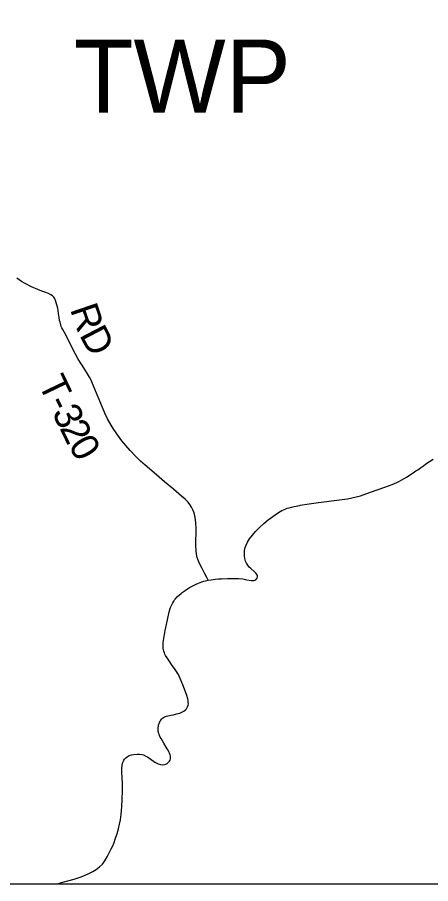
# Model space of a CAD drawing. Extents: x -10.5 to 40.6, y -3.2 to 22.
# Drawn here: x -6.111 to -5.263, y 14.1 to 15.878 of the extents above; entities that cross this region are included whole.
import ezdxf

# ---------------------------------------------------------------- set-up
doc = ezdxf.new("R2010")
doc.units = 0
for name, color, linetype in [('GM_X_County_Road', 7, 'Continuous'), ('GM_X_Township_Road', 7, 'Continuous'), ('GM_X_Township_Road_Text', 7, 'Continuous'), ('GM_X_Township_Text', 7, 'Continuous')]:
    doc.layers.add(name, color=color, linetype=linetype)

msp = doc.modelspace()

# ---------------------------------------------------------------- linework, layer by layer
at = {"layer": 'GM_X_County_Road'}
for points in [[(-5.7194, 14.7225), (-5.7136, 14.7237), (-5.7049, 14.7248), (-5.6982, 14.7254), (-5.6924, 14.7254), (-5.68, 14.7259), (-5.6651, 14.7263), (-5.6571, 14.7261), (-5.6484, 14.7252), (-5.6398, 14.7237), (-5.6313, 14.7221), (-5.6289, 14.7219), (-5.627, 14.7219), (-5.6254, 14.7222), (-5.6234, 14.7227), (-5.6216, 14.7237), (-5.6193, 14.7261), (-5.6189, 14.727), (-5.6181, 14.7296), (-5.6185, 14.7323), (-5.6193, 14.7343), (-5.6209, 14.7366), (-5.6253, 14.7408), (-5.6319, 14.7466), (-5.6351, 14.7497), (-5.6382, 14.7537), (-5.6406, 14.7574), (-5.6428, 14.762), (-5.6443, 14.7675), (-5.645, 14.7726), (-5.6452, 14.7783), (-5.6446, 14.7839), (-5.6433, 14.7895), (-5.6417, 14.7943), (-5.6387, 14.8006), (-5.6344, 14.8075), (-5.6287, 14.815), (-5.6223, 14.8226), (-5.6144, 14.8306), (-5.6052, 14.839), (-5.596, 14.8465), (-5.5816, 14.8571), (-5.5754, 14.8613), (-5.5684, 14.8655), (-5.5615, 14.8686), (-5.5575, 14.8702), (-5.5529, 14.8715), (-5.5481, 14.8728), (-5.5429, 14.874), (-5.5315, 14.8763), (-5.5307, 14.8764), (-5.5123, 14.8796), (-5.4932, 14.8823), (-5.4556, 14.8871), (-5.4335, 14.8898), (-5.4243, 14.8915), (-5.4153, 14.8936), (-5.4064, 14.8961), (-5.3859, 14.9031), (-5.3565, 14.9134), (-5.342, 14.9189), (-5.3324, 14.9231), (-5.3268, 14.9256), (-5.322, 14.9284), (-5.3124, 14.9341), (-5.2984, 14.9432), (-5.2933, 14.9468), (-5.2892, 14.9495), (-5.2834, 14.9535), (-5.2775, 14.9577), (-5.2723, 14.9612), (-5.2652, 14.966), (-5.2574, 14.9712)], [(-5.8117, 14.5951), (-5.8107, 14.6032), (-5.8078, 14.6192), (-5.8032, 14.6411), (-5.7992, 14.6581), (-5.7966, 14.6664), (-5.7936, 14.6734), (-5.7921, 14.6765), (-5.7902, 14.6794), (-5.7883, 14.6823), (-5.787, 14.6841), (-5.7824, 14.6893), (-5.7785, 14.693), (-5.7752, 14.6956), (-5.7727, 14.6973), (-5.7667, 14.7017), (-5.762, 14.7048), (-5.7578, 14.7074), (-5.7479, 14.7127), (-5.7439, 14.7147), (-5.7395, 14.7166), (-5.7357, 14.7181), (-5.7323, 14.7193), (-5.7286, 14.7204), (-5.7249, 14.7216), (-5.7194, 14.7225)], [(-6.0287, 14.1), (-6.0205, 14.1022), (-5.9942, 14.1094), (-5.9824, 14.1131), (-5.9732, 14.1168), (-5.9631, 14.1216), (-5.956, 14.1252), (-5.9492, 14.1294), (-5.9424, 14.1346), (-5.9367, 14.1403), (-5.9319, 14.1466), (-5.9268, 14.155), (-5.9225, 14.1631), (-5.9184, 14.1712), (-5.916, 14.1764), (-5.9127, 14.1842), (-5.9103, 14.191), (-5.9063, 14.2027), (-5.9035, 14.2122), (-5.9012, 14.2218), (-5.8996, 14.2309), (-5.8982, 14.242), (-5.897, 14.2574), (-5.8961, 14.2735), (-5.8955, 14.2896), (-5.8955, 14.3057), (-5.896, 14.3175), (-5.8966, 14.3287), (-5.8967, 14.3363), (-5.8961, 14.3426), (-5.8951, 14.347), (-5.8936, 14.3511), (-5.8923, 14.3533), (-5.891, 14.3555), (-5.8883, 14.3583), (-5.8858, 14.3604), (-5.8813, 14.3628), (-5.877, 14.3641), (-5.872, 14.3651), (-5.865, 14.3656), (-5.8602, 14.3657), (-5.8558, 14.365), (-5.8525, 14.3641), (-5.8472, 14.3619), (-5.8439, 14.3601), (-5.8413, 14.3582), (-5.8362, 14.3546), (-5.8316, 14.3513), (-5.8292, 14.3495), (-5.8259, 14.3478), (-5.8221, 14.346), (-5.8175, 14.3446), (-5.8127, 14.344), (-5.8091, 14.3445), (-5.8063, 14.3452), (-5.8037, 14.3464), (-5.8014, 14.3483), (-5.7987, 14.3513), (-5.7978, 14.3535), (-5.7969, 14.356), (-5.7966, 14.3581), (-5.7971, 14.3617), (-5.7978, 14.3642), (-5.7991, 14.3676), (-5.8004, 14.3708), (-5.8019, 14.3737), (-5.8035, 14.377), (-5.8054, 14.3802), (-5.8107, 14.3886), (-5.8162, 14.3976), (-5.8179, 14.4009), (-5.8192, 14.4038), (-5.8203, 14.4069), (-5.8212, 14.4098), (-5.8218, 14.4142), (-5.822, 14.4164), (-5.822, 14.4193), (-5.8215, 14.4237), (-5.8211, 14.4262), (-5.8203, 14.4287), (-5.8189, 14.4322), (-5.8178, 14.4342), (-5.8168, 14.4357), (-5.8154, 14.4376), (-5.8135, 14.4394), (-5.8113, 14.4411), (-5.8091, 14.4423), (-5.8073, 14.443), (-5.8052, 14.4437), (-5.7959, 14.4459), (-5.7907, 14.4467), (-5.7843, 14.4482), (-5.7779, 14.45), (-5.7734, 14.4519), (-5.7692, 14.4543), (-5.766, 14.457), (-5.764, 14.4591), (-5.7627, 14.4612), (-5.7616, 14.4632), (-5.7606, 14.4665), (-5.7601, 14.4693), (-5.7602, 14.4727), (-5.7605, 14.4764), (-5.7611, 14.4794), (-5.7631, 14.4859), (-5.7702, 14.5044), (-5.7746, 14.516), (-5.7768, 14.5208), (-5.7789, 14.5256), (-5.7806, 14.5289), (-5.7825, 14.5321), (-5.7845, 14.5356), (-5.7871, 14.5394), (-5.7946, 14.55), (-5.7997, 14.557), (-5.8039, 14.5633), (-5.8067, 14.5682), (-5.8081, 14.571), (-5.8092, 14.5739), (-5.8102, 14.5769), (-5.811, 14.5801), (-5.8115, 14.5835), (-5.8119, 14.5876), (-5.812, 14.5917), (-5.8117, 14.5951)]]:
    msp.add_lwpolyline(points, dxfattribs=at)
at = {"layer": 'GM_X_Township_Road'}
msp.add_lwpolyline([(-5.7194, 14.7225), (-5.7222, 14.7282), (-5.726, 14.736), (-5.7327, 14.7479), (-5.7374, 14.7573), (-5.7401, 14.7635), (-5.742, 14.7694), (-5.7434, 14.7761), (-5.7441, 14.7834), (-5.7445, 14.7946), (-5.7441, 14.8287), (-5.7446, 14.8398), (-5.7455, 14.8472), (-5.7469, 14.8551), (-5.7485, 14.8611), (-5.7507, 14.8669), (-5.7535, 14.8725), (-5.7568, 14.8777), (-5.7606, 14.8826), (-5.7667, 14.8888), (-5.7741, 14.8954), (-5.7851, 14.9045), (-5.7908, 14.9092), (-5.8088, 14.9245), (-5.8258, 14.9391), (-5.8491, 14.9587), (-5.8582, 14.967), (-5.8683, 14.9771), (-5.8793, 14.9888), (-5.8887, 14.9994), (-5.8965, 15.009), (-5.9047, 15.02), (-5.9129, 15.0317), (-5.9189, 15.0411), (-5.9258, 15.0536), (-5.9315, 15.0653), (-5.9365, 15.0774), (-5.9542, 15.1197), (-5.9569, 15.1263), (-5.9599, 15.1329), (-5.9633, 15.1395), (-5.9673, 15.1465), (-5.9725, 15.1549), (-5.9782, 15.1638), (-5.9816, 15.169), (-5.9868, 15.1775), (-5.992, 15.1867), (-5.9995, 15.201), (-6.0111, 15.225), (-6.0177, 15.2368), (-6.0197, 15.2403), (-6.021, 15.2431), (-6.0222, 15.2467), (-6.0235, 15.252), (-6.0244, 15.2556), (-6.0253, 15.2617), (-6.0264, 15.2703), (-6.0283, 15.2807), (-6.0305, 15.2898), (-6.0319, 15.2947), (-6.0334, 15.2985), (-6.0349, 15.3012), (-6.0364, 15.3033), (-6.0391, 15.3059), (-6.0426, 15.3085), (-6.047, 15.3108), (-6.0493, 15.3117), (-6.0527, 15.313), (-6.0608, 15.3159), (-6.0688, 15.3191), (-6.0818, 15.3249), (-6.0951, 15.3316), (-6.1026, 15.3359), (-6.1124, 15.3424)], dxfattribs=at)
at = {"layer": 'GM_X_Township_Text'}
msp.add_lwpolyline([(-6.1874, 16.891), (-6.1985, 16.7494), (-6.1956, 16.4198), (-6.1883, 16.2366), (-6.1993, 15.3843), (-6.2122, 14.1), (-3.7445, 14.1), (-3.7445, 16.8499)], dxfattribs=at)

# ---------------------------------------------------------------- texts
at = {"layer": 'GM_X_Township_Road_Text'}
for s, rotation, p in [('R', 288.8916, (-6.0034, 15.279)), ('D', 297.561, (-5.9847, 15.2263)), ('T', 295.6163, (-6.0693, 15.1264)), ('-', 295.6514, (-6.051, 15.0881)), ('3', 295.766, (-6.0408, 15.0669)), ('2', 296.2976, (-6.0253, 15.0349)), ('0', 300.5873, (-6.0076, 14.9994))]:
    msp.add_text(s, height=0.0568, rotation=rotation, dxfattribs=at).set_placement(p)
at = {"layer": 'GM_X_Township_Text'}
msp.add_text('TWP', height=0.15, rotation=0, dxfattribs=at).set_placement((-5.9953, 15.6821))

doc.saveas('drawing.dxf')
